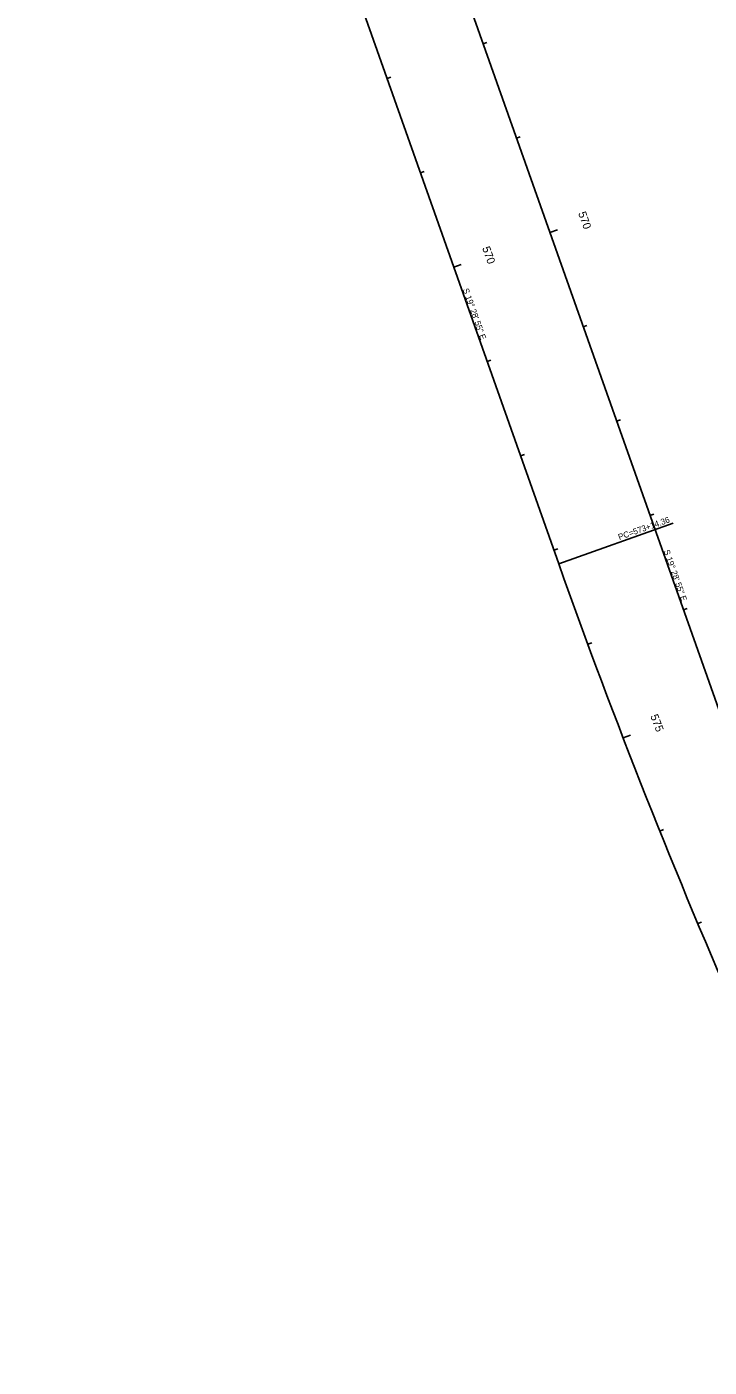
# Model space of a CAD drawing. Extents: x 2004390 to 2008791, y 1133870 to 1140084.
# Drawn here: x 2005719 to 2006401, y 1135092 to 1136432 of the extents above; entities that cross this region are included whole.
import ezdxf

# ---------------------------------------------------------------- set-up
doc = ezdxf.new("R2010")
doc.units = 0
for name, color, linetype in [('RD_HC_Cl', 7, 'Continuous'), ('RD_HC_Data', 7, 'Continuous'), ('RD_HC_Data_Tic', 7, 'Continuous'), ('RD_HC_TX_Sta50', 7, 'Continuous')]:
    doc.layers.add(name, color=color, linetype=linetype)

msp = doc.modelspace()

# ---------------------------------------------------------------- linework, layer by layer
at = {"layer": 'RD_HC_Cl'}
for p, q in [((2005036.1, 1139633.5), (2007075.2, 1133869.8)), ((2005747, 1137318.2), (2006250.3, 1135895.5))]:
    msp.add_line(p, q, dxfattribs=at)
msp.add_arc((2012591.2, 1138138.7), 6726, 199.48201, 203.72857, dxfattribs=at)
at = {"layer": 'RD_HC_Data'}
msp.add_line((2006250.3, 1135895.5), (2006364.7, 1135936), dxfattribs=at)
at = {"layer": 'RD_HC_Data_Tic'}
for p, q in [((2006174.7, 1136415.2), (2006178.5, 1136416.5)), ((2006078.8, 1136380.4), (2006082.6, 1136381.8)), ((2006208, 1136320.9), (2006211.8, 1136322.2)), ((2006112.1, 1136286.1), (2006115.9, 1136287.5)), ((2006241.4, 1136226.6), (2006248.9, 1136229.3)), ((2006145.5, 1136191.9), (2006153, 1136194.5)), ((2006274.7, 1136132.4), (2006278.5, 1136133.7)), ((2006178.8, 1136097.6), (2006182.6, 1136098.9)), ((2006308.1, 1136038.1), (2006311.9, 1136039.4)), ((2006212.2, 1136003.3), (2006216, 1136004.7)), ((2006341.4, 1135943.8), (2006345.2, 1135945.1)), ((2006245.5, 1135909), (2006249.3, 1135910.4)), ((2006374.8, 1135849.5), (2006378.6, 1135850.9)), ((2006279.4, 1135815), (2006283.2, 1135816.3)), ((2006314.7, 1135721.4), (2006322.1, 1135724.2)), ((2006351.3, 1135628.3), (2006355, 1135629.8)), ((2006389.3, 1135535.8), (2006393, 1135537.4))]:
    msp.add_line(p, q, dxfattribs=at)

# ---------------------------------------------------------------- texts
at = {"layer": 'RD_HC_Data'}
for s, rotation, p in [('S 19%%d 28\' 55" E', 289.482, (2006154.4, 1136169.6)), ('PC=573+14.36', 19.482, (2006310.9, 1135919.1)), ('S 19%%d 28\' 55" E', 289.482, (2006355, 1135908.3))]:
    msp.add_text(s, height=6, rotation=rotation, dxfattribs=at).set_placement(p)
at = {"layer": 'RD_HC_TX_Sta50'}
for s, rotation, p in [('570', 289.482, (2006269.6, 1136245.9)), ('570', 289.482, (2006173.7, 1136211.1)), ('575', 291.0634, (2006341.6, 1135743.3))]:
    msp.add_text(s, height=8, rotation=rotation, dxfattribs=at).set_placement(p)

doc.saveas('drawing.dxf')
